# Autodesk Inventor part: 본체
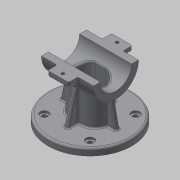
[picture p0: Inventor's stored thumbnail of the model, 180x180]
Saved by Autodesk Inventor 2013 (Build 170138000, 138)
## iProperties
Created: 2015-12
Part Number: 본체
Material: 일반
Document SubType Name: Modeling
Designer: mduedu
Density: 1 g/cm^3
Mass: 214.357 g
Surface Area: 555.601 cm^2
Volume: 214.357 cm^3
Author: mduedu
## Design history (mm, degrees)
sketch "스케치1"
  geometry: L1 (45, 40)-(-45, 40); L2 (-45, 40)-(-45, -40); L3 (-45, -40)-(45, -40); L4 (45, -40)-(45, 40); L5 (45, 40)-(-45, -40); L6 (-45, 40)-(45, -40); 2 further points
  constraints: 12 end point, 2 midpoint, 2 parallel, 1 coincident, 1 horizontal, 1 perpendicular, 3 other
  dimensions: "d0" = 90 distance of L2.end L3.end; "d2" = 80 distance of L1.end L2.end
extrude "돌출1" new body sketch "스케치1" distance "d3" = 10; taper "d4" = 0 deg
sketch "스케치2"
  geometry: C1 r 32.5 at (80, 0); 1 further point
  constraints: 1 centre point
  dimensions: "d5" = 65 diameter of C1; "d116" = 80 distance of point (0, 0) C1.centre
extrude "돌출2" join sketch "스케치2" stored distance "d7" = 75; taper "d8" = 0 deg
sketch "스케치3"
  geometry: L1 (-27.5, -20)-(27.5, -20); L2 (27.5, -20)-(27.5, 20); L3 (27.5, 20)-(-27.5, 20); L4 (-27.5, 20)-(-27.5, -20); L5 (-27.5, -20)-(27.5, 20); L6 (27.5, -20)-(-27.5, 20); 1 further point
  constraints: 12 end point, 2 midpoint, 2 parallel, 1 horizontal, 1 perpendicular
  dimensions: "d9" = 55 distance of L2.end L3.end; "d11" = 40 distance of L1.end L2.end
extrude "돌출3" new body sketch "스케치3" stored distance "d12" = 75; taper "d13" = 0 deg
fillet "모깎기1"
fillet "모깎기2"
feature "결합1"
  node "솔리드2"
sketch "스케치4"
  geometry: L1 (-37.5, 47.5)-(37.5, 47.5) reference; L2 (32.5, 47.5)-(40.208, 10); L3 (37.5, 47.5)-(37.5, 112.5) reference; L4 (60.208, 0)-(60.208, 10) reference; L5 (60.208, 10)-(-60.208, 10) reference; 1 further point
  constraints: 2 end point, 2 point on line
  dimensions: "d15" = 5 distance from line of L2.start L3; "d117" = 20 distance from line of L2.end L4
sketch "스케치5"
  geometry: L1 (10, 35.208)-(56.729, 22.687); L2 (0, 60.208)-(10, 60.208) reference; L3 (10, -60.208)-(10, 60.208) reference; 2 further points
  constraints: 2 end point, 1 point on line, 2 other
  dimensions: "d118" = 25 distance from line of L1.start L2; "d119" = 75 deg angle of L1 L3
feature "리브1" dims "d19" = 1, "d20" = 6, "d21" = 0, "d22" = 0, "d23" = 1, "d24" = 1
feature "리브2" dims "d25" = 1, "d26" = 6, "d27" = 0, "d28" = 0, "d29" = 1, "d30" = 1
fillet "모깎기4" dims "d31" = 2
fillet "모깎기5" dims "d32" = 2
fillet "모깎기6" dims "d33" = 2
sketch "스케치6"
  geometry: L1 (0, 0)-(-32.88, 32.88); L2 (0, 0)-(-46.5, 0); A1 r 46.5 centre (0, 0) between (-32.88, 32.88) and (-46.5, 0); 5 further points
  constraints: 4 end point, 2 coincident, 2 point on circle, 1 centre point, 1 horizontal, 5 other
  dimensions: "d120" = 93 diameter of A1; "d122" = 45 deg angle of L1 L2; "d126" = 360 deg dimension on point (0, 0) point (-32.88, 32.88) (derived)
hole "구멍1" sketch "스케치6" at (-32.88, 32.88), (-32.88, -32.88), (32.88, -32.88), (32.88, 32.88) diameter "d34" = 7; stored, may be unused: countersink angle "d38" = 90 deg, drill point angle "d40" = 118 deg; dims "d35" = 6, "d36" = 12, "d37" = 3, "d39" = 8
fillet "모깎기13" dims "d131" = 3
hole "구멍2" diameter "d44" = 45; stored, may be unused: countersink angle "d48" = 90 deg, drill point angle "d50" = 118 deg; dims "d42" = 10, "d43" = 10, "d45" = 6, "d46" = 4, "d47" = 2, "d49" = 8
sketch "스케치7" dims "d52" = 26.5
  geometry: L1 (0, 0)-(32.5, 0); L2 (0, 0)-(22.981, 22.981); A1 r 32.5 centre (0, 0) between (32.5, 0) and (22.981, 22.981) reference; 3 further points
  constraints: 4 end point, 2 point on circle, 1 coincident, 1 horizontal, 1 point on line, 3 other
  dimensions: "d51" = 45 deg angle of L2 L1
hole "구멍3" sketch "스케치7" at (18.738, 18.738) diameter "d54" = 2.459; stored, may be unused: countersink angle "d58" = 90 deg, drill point angle "d60" = 118 deg; dims "d55" = 8, "d56" = 4, "d57" = 2, "d59" = 10
sketch "스케치8"
  geometry: L1 (72.5, 31.623)-(72.5, 46); L2 (72.5, 46)-(87.5, 46); L3 (87.5, 46)-(87.5, 31.623); A1 r 32.5 centre (80, 0) between (87.5, 31.623) and (72.5, 31.623) reference; 2 further points
  constraints: 6 end point, 2 point on circle, 1 horizontal, 1 midpoint, 1 parallel, 1 vertical, 1 vertical alignment
  dimensions: "d64" = 15 distance of L1.end L2.end; "d66" = 46 distance from line of L2 A1.centre
extrude "돌출4" join sketch "스케치8" stored distance "d67" = 30; taper "d68" = 0 deg
fillet "모깎기8" dims "d69" = 3
fillet "모깎기9" dims "d70" = 2
node "작업 평면2"
sketch "스케치16"
  geometry: L1 (33.166, 72.5)-(44, 72.5) reference; L2 (42.5, 72.5)-(28.53, 64.434); L3 (46, 75.5)-(46, 84.5) reference; 2 further points
  constraints: 2 end point, 1 point on line, 2 other
  dimensions: "d138" = 30 deg angle of L2 L1; "d139" = 3.5 distance from line of L2.start L3
feature "리브3" sketch "스케치16" dims "d140" = 1, "d141" = 3, "d142" = 0, "d143" = 0, "d144" = 1, "d145" = 1
fillet "모깎기14" dims "d146" = 1
fillet "모깎기15" dims "d147" = 1
sketch "스케치9"
  geometry: L1 (-76, 82.5)-(76, 82.5); L2 (76, 82.5)-(76, 0); L3 (76, 0)-(-76, 0); L4 (-76, 0)-(-76, 82.5); L5 (-46, 4.5)-(-46, -4.5) reference; C1 r 32.5 at (0, 0) reference; 2 further points
  constraints: 8 end point, 2 parallel, 1 coincident, 1 horizontal, 1 midpoint, 1 perpendicular
  dimensions: "d71" = 50 distance edge to line of C1 L1; "d72" = 30 distance between parallel lines of L4 L5
extrude "돌출5" cut sketch "스케치9" stored distance "d73" = 0; taper "d74" = 0 deg
node "작업 평면1"
sketch "스케치10"
  geometry: L1 (-7.5, 15)-(7.5, 15); L2 (-7.5, -15)-(7.5, -15); A1 r 20 centre (-7.5, 0) between (-7.5, 20) and (-26.977, 4.545) reference; A2 r 20 centre (7.5, 0) between (26.977, 4.545) and (7.5, 20) reference; A3 r 15 centre (-7.5, 0) between (-7.5, 15) and (-7.5, -15); A4 r 15 centre (7.5, 0) between (7.5, -15) and (7.5, 15); 1 further point
  constraints: 7 point on circle, 4 end point, 4 tangent, 3 point on line, 2 centre point, 2 coincident, 1 horizontal
  dimensions: "d77" = 5 radial gap between concentric circles of A3 A1
extrude "돌출6" cut sketch "스케치10" stored distance "d78" = 50; taper "d79" = 0 deg
fillet "모깎기10" dims "d80" = 3
sketch "스케치11"
  geometry: 2 further points
  constraints: 1 coincident
hole "구멍4" sketch "스케치11" at (0, 0) diameter "d81" = 12; stored, may be unused: countersink angle "d85" = 90 deg, drill point angle "d87" = 118 deg; dims "d82" = 8, "d83" = 40, "d84" = 10, "d86" = 10
sketch "스케치12"
  geometry: C1 r 10 at (0, 0); 1 further point
  constraints: 1 centre point, 1 coincident
  dimensions: "d88" = 20 diameter of C1
extrude "돌출7" cut sketch "스케치12" distance "d89" = 5; taper "d90" = 0 deg
chamfer "모따기1" distance "d91" = 1; stored, may be unused: second distance "d92" = 2, angle "d93" = 45 deg
fillet "모깎기11" dims "d94" = 0.5
sketch "스케치13"
  geometry: L1 (-3, 10.834)-(-3, 1.039) reference; L2 (27, 1.039)-(27, 10.834) reference; L3 (-3, 5.936)-(27, 5.936); L4 (24, 12.834)-(0, 12.834) reference; L5 (12, 12.834)-(12, -33.166); 1 further point
  constraints: 4 end point, 4 midpoint, 1 perpendicular, 1 point on line
hole "구멍5" sketch "스케치13" at (12, 5.936) diameter "d101" = 4.5; stored, may be unused: countersink angle "d105" = 90 deg, drill point angle "d107" = 0 deg; dims "d102" = 6, "d103" = 4, "d104" = 2, "d106" = 8
fillet "모깎기12" dims "d115" = 0.3
node "솔리드1"
mirror "대칭1"
mirror "대칭2"
pattern_circular "원형 패턴1" dims angle "d62" = 360 deg
mirror "대칭3"
mirror "대칭7"
mirror "대칭4"
mirror "대칭6"
other parameters: "d137" = -5
